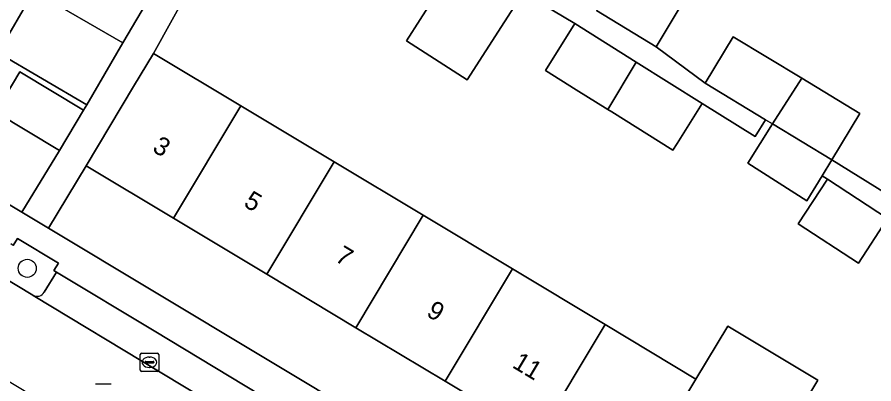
# Model space of a CAD drawing. Extents: x 160102 to 160934, y 382045 to 382923.
# Drawn here: x 160356.4 to 160402.88, y 382269.48 to 382289.36 of the extents above; entities that cross this region are included whole.
import ezdxf

# ---------------------------------------------------------------- set-up
doc = ezdxf.new("R2010")
doc.units = 0
for name, color, linetype in [('IMGEO_Boom', 7, 'Continuous'), ('IMGEO_Erf', 7, 'Continuous'), ('IMGEO_Groenvoorziening', 7, 'Continuous'), ('IMGEO_Kolk', 7, 'Continuous'), ('IMGEO_Pand', 7, 'Continuous'), ('IMGEO_Pand_nummerreeks', 7, 'Continuous'), ('IMGEO_Parkeervlak_open', 7, 'Continuous'), ('IMGEO_Rijbaan_lokaal_open', 7, 'Continuous'), ('IMGEO_Rioolput', 7, 'Continuous'), ('IMGEO_Voetpad_open', 7, 'Continuous')]:
    doc.layers.add(name, color=color, linetype=linetype)

msp = doc.modelspace()

# ---------------------------------------------------------------- linework, layer by layer
at = {"layer": 'IMGEO_Boom'}
msp.add_circle((160356.952, 382275.745), 0.489, dxfattribs=at)
at = {"layer": 'IMGEO_Erf'}
for points in [[(160344.039, 382286.352), (160356.664, 382278.779), (160358.695, 382282.138), (160355.236, 382284.213), (160356.54, 382286.388), (160359.999, 382284.313), (160360.175, 382284.614), (160355.353, 382287.424), (160357.305, 382290.773), (160362.134, 382287.959), (160363.655, 382290.557), (160361.206, 382291.98), (160363.135, 382295.3), (160366.118, 382300.431), (160365.51, 382300.785), (160366.666, 382302.692)], [(160369.034, 382296.857), (160363.795, 382287.392), (160368.538, 382284.547), (160373.592, 382281.515), (160378.424, 382278.617), (160383.267, 382275.712), (160388.295, 382272.696), (160393.223, 382269.74), (160394.947, 382272.613), (160399.835, 382269.679), (160398.112, 382266.807), (160403.023, 382263.861)], [(160403.624, 382278.446), (160402.043, 382276.022), (160398.775, 382278.153), (160400.355, 382280.577), (160400.066, 382280.766), (160399.241, 382279.404), (160396.036, 382281.443), (160397.387, 382283.568), (160397.001, 382283.801), (160396.444, 382282.88), (160393.564, 382284.683), (160392.202, 382282.507), (160391.976, 382282.146), (160388.664, 382284.217), (160388.449, 382284.351), (160386.736, 382285.423), (160385.07, 382286.465), (160386.658, 382289.004), (160383.854, 382290.698), (160380.822, 382285.961), (160377.525, 382288.071), (160379.001, 382290.4)], [(160392.59, 382290.269), (160391.068, 382287.755), (160393.727, 382285.783), (160395.249, 382288.297), (160398.964, 382286.048), (160402.111, 382284.144), (160400.589, 382281.63), (160407.22, 382277.527)]]:
    msp.add_lwpolyline(points, dxfattribs=at)
msp.add_lwpolyline([(160389.569, 382263.65), (160384.642, 382266.606), (160379.614, 382269.622), (160374.771, 382272.527), (160369.939, 382275.425), (160364.885, 382278.457), (160360.142, 382281.302), (160358.109, 382277.912), (160404.646, 382250), (160407.669, 382248.188), (160409.699, 382251.575), (160404.429, 382254.736), (160399.369, 382257.771), (160394.458, 382260.717)], close=True, dxfattribs=at)
at = {"layer": 'IMGEO_Groenvoorziening'}
for points in [[(160357.868, 382274.448), (160358.536, 382275.545), (160358.401, 382275.626), (160358.645, 382276.022), (160356.427, 382277.363), (160356.19, 382276.984), (160356.055, 382277.065)], [(160355.526, 382275.346), (160357.259, 382274.289)]]:
    msp.add_lwpolyline(points, dxfattribs=at)
msp.add_arc((160357.485, 382274.669), 0.442, 239.2316, 330.0331, dxfattribs=at)
at = {"layer": 'IMGEO_Kolk'}
for p, q in [((160363.08, 382270.228), (160363.08, 382271.08)), ((160363.155, 382271.154), (160364.007, 382271.154)), ((160363.568, 382270.934), (160363.593, 382270.934)), ((160364.081, 382271.08), (160364.081, 382270.228)), ((160363.339, 382270.648), (160363.339, 382270.66)), ((160363.777, 382270.611), (160363.379, 382270.611)), ((160363.382, 382270.697), (160363.78, 382270.697)), ((160363.823, 382270.66), (160363.823, 382270.648)), ((160364.007, 382270.154), (160363.155, 382270.154)), ((160363.591, 382270.374), (160363.566, 382270.374))]:
    msp.add_line(p, q, dxfattribs=at)
for points in [[(160363.08, 382270.228), (160363.08, 382271.08)], [(160363.155, 382271.154), (160364.007, 382271.154)], [(160364.081, 382271.08), (160364.081, 382270.228)], [(160364.007, 382270.154), (160363.155, 382270.154)]]:
    msp.add_lwpolyline(points, dxfattribs=at)
for centre, radius, start, end in [((160363.157, 382271.078), 0.0765, 91.552, 178.448), ((160363.157, 382271.078), 0.0765, 91.552, 178.448), ((160364.005, 382271.078), 0.0765, 1.552, 88.448), ((160364.005, 382271.078), 0.0765, 1.552, 88.448), ((160363.379, 382270.657), 0.0403, 85.8775, 175.7526), ((160363.376, 382270.647), 0.0366, 178.938, 274.7102), ((160363.78, 382270.654), 0.043, 264.8664, 352.4533), ((160363.784, 382270.659), 0.0386, 1.7309, 96.639), ((160363.157, 382270.23), 0.0765, 181.552, 268.448), ((160363.157, 382270.23), 0.0765, 181.552, 268.448), ((160364.005, 382270.23), 0.0765, 271.552, 358.448), ((160364.005, 382270.23), 0.0765, 271.552, 358.448)]:
    msp.add_arc(centre, radius, start, end, dxfattribs=at)
for centre, major_axis, ratio, start_param, end_param in [((160363.567, 382270.654), (-0.387, 0.002), 0.722429, 4.712389, 7.853982), ((160363.592, 382270.654), (-0.39, 0.002), 0.717154, 1.570796, 4.712389)]:
    msp.add_ellipse(centre, major_axis=major_axis, ratio=ratio, start_param=start_param, end_param=end_param, dxfattribs=at)
at = {"layer": 'IMGEO_Pand'}
for points in [[(160378.944, 382290.437), (160379.001, 382290.4), (160377.525, 382288.071), (160380.822, 382285.961), (160383.854, 382290.698), (160380.419, 382292.897)], [(160387.838, 382289.71), (160391.068, 382287.755), (160392.59, 382290.269), (160389.415, 382292.19)], [(160362.134, 382287.959), (160357.305, 382290.773), (160355.353, 382287.424), (160360.175, 382284.614)], [(160389.99, 382286.92), (160386.658, 382289.004), (160385.07, 382286.465), (160386.736, 382285.423), (160388.449, 382284.351)], [(160398.964, 382286.048), (160395.249, 382288.297), (160393.727, 382285.783), (160397.001, 382283.801), (160397.387, 382283.568)], [(160364.885, 382278.457), (160368.538, 382284.547), (160363.795, 382287.392), (160362.714, 382285.59), (160360.142, 382281.302)], [(160393.564, 382284.683), (160389.99, 382286.92), (160388.449, 382284.351), (160388.664, 382284.217), (160391.976, 382282.146), (160392.202, 382282.507)], [(160355.236, 382284.213), (160358.695, 382282.138), (160359.999, 382284.313), (160356.54, 382286.388)], [(160397.387, 382283.568), (160400.589, 382281.63), (160402.111, 382284.144), (160398.964, 382286.048)], [(160364.885, 382278.457), (160369.939, 382275.425), (160373.592, 382281.515), (160368.538, 382284.547)], [(160397.387, 382283.568), (160396.036, 382281.443), (160399.241, 382279.404), (160400.066, 382280.766), (160400.589, 382281.63)], [(160374.771, 382272.527), (160378.424, 382278.617), (160373.592, 382281.515), (160369.939, 382275.425)], [(160400.355, 382280.577), (160398.775, 382278.153), (160402.043, 382276.022), (160403.624, 382278.446)], [(160374.771, 382272.527), (160379.614, 382269.622), (160383.267, 382275.712), (160378.424, 382278.617)], [(160383.267, 382275.712), (160379.614, 382269.622), (160384.642, 382266.606), (160388.295, 382272.696)], [(160388.295, 382272.696), (160384.642, 382266.606), (160389.569, 382263.65), (160393.223, 382269.74)], [(160398.112, 382266.807), (160399.835, 382269.679), (160394.947, 382272.613), (160393.223, 382269.74), (160389.569, 382263.65), (160394.458, 382260.717)]]:
    msp.add_lwpolyline(points, close=True, dxfattribs=at)
at = {"layer": 'IMGEO_Parkeervlak_open'}
for points in [[(160358.536, 382275.545), (160357.868, 382274.448)], [(160383.955, 382258.687), (160384.647, 382259.799), (160372.063, 382267.382), (160363.843, 382272.35), (160358.536, 382275.545)], [(160357.259, 382274.289), (160357.276, 382274.276), (160364.164, 382270.125), (160371.204, 382265.869), (160372.99, 382264.789), (160375.974, 382262.984), (160384.107, 382258.065)]]:
    msp.add_lwpolyline(points, dxfattribs=at)
msp.add_arc((160357.485, 382274.669), 0.442, 239.2316, 330.0331, dxfattribs=at)
at = {"layer": 'IMGEO_Rijbaan_lokaal_open'}
msp.add_lwpolyline([(160357.259, 382274.289), (160355.526, 382275.346), (160355.493, 382275.363), (160349.36, 382279.058), (160347.392, 382280.232), (160346.737, 382280.632), (160344.356, 382276.584), (160345.027, 382276.18), (160346.971, 382275.028), (160363.396, 382265.134), (160370.614, 382260.795), (160372.99, 382264.789), (160371.204, 382265.869), (160364.164, 382270.125), (160357.276, 382274.276)], close=True, dxfattribs=at)
at = {"layer": 'IMGEO_Rioolput'}
msp.add_line((160360.655, 382269.483), (160361.507, 382269.483), dxfattribs=at)
msp.add_lwpolyline([(160360.655, 382269.483), (160361.507, 382269.483)], dxfattribs=at)
at = {"layer": 'IMGEO_Voetpad_open'}
for points in [[(160363.655, 382290.557), (160362.134, 382287.959), (160360.175, 382284.614), (160359.999, 382284.313), (160358.695, 382282.138), (160356.664, 382278.779), (160358.109, 382277.912), (160360.142, 382281.302), (160362.714, 382285.59), (160363.795, 382287.392), (160369.034, 382296.857)], [(160383.854, 382290.698), (160386.658, 382289.004), (160389.99, 382286.92), (160393.564, 382284.683), (160396.444, 382282.88), (160397.001, 382283.801), (160393.727, 382285.783), (160391.068, 382287.755), (160387.838, 382289.71)], [(160358.109, 382277.912), (160356.664, 382278.779), (160344.039, 382286.352)], [(160407.22, 382277.527), (160400.589, 382281.63), (160400.066, 382280.766), (160400.355, 382280.577), (160403.624, 382278.446)], [(160418.905, 382241.451), (160408.838, 382247.487), (160407.669, 382248.188), (160404.646, 382250), (160358.109, 382277.912)], [(160356.19, 382276.984), (160356.427, 382277.363), (160358.645, 382276.022), (160358.401, 382275.626), (160358.536, 382275.545), (160363.843, 382272.35), (160372.063, 382267.382), (160384.647, 382259.799), (160384.709, 382259.761), (160384.942, 382260.146), (160388.043, 382258.265), (160387.806, 382257.873), (160387.835, 382257.855), (160393.131, 382254.669), (160396.73, 382252.489), (160396.839, 382252.423), (160397.08, 382252.823), (160399.392, 382251.42), (160400.438, 382250.792), (160400.191, 382250.395), (160400.277, 382250.343), (160405.318, 382247.314)]]:
    msp.add_lwpolyline(points, dxfattribs=at)

# ---------------------------------------------------------------- texts
at = {"layer": 'IMGEO_Pand_nummerreeks'}
for s, p in [('3', (160363.68, 382282.119)), ('5', (160368.635, 382279.146)), ('7', (160373.591, 382276.173)), ('9', (160378.547, 382273.2)), ('11', (160383.206, 382270.405))]:
    msp.add_text(s, height=1, rotation=329.0424, dxfattribs=at).set_placement(p)

doc.saveas('drawing.dxf')
